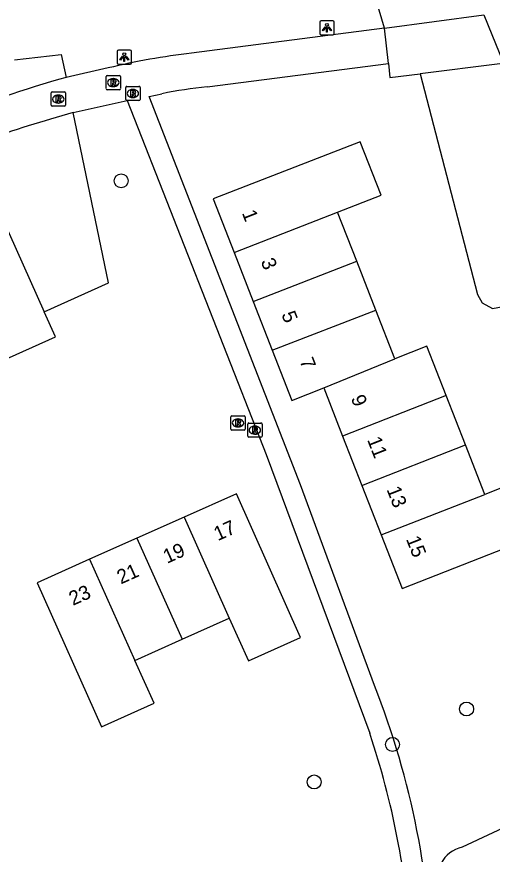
# Model space of a CAD drawing. Extents: x 159451 to 160663, y 388402 to 389723.
# Drawn here: x 159555.6 to 159588.9, y 389199.9 to 389258.6 of the extents above; entities that cross this region are included whole.
import ezdxf

# ---------------------------------------------------------------- set-up
doc = ezdxf.new("R2010")
doc.units = 0
for name, color, linetype in [('IMGEO_Boom', 7, 'Continuous'), ('IMGEO_Lichtpunt', 7, 'Continuous'), ('IMGEO_Meer_plas_ven_vijver', 7, 'Continuous'), ('IMGEO_Pand', 7, 'Continuous'), ('IMGEO_Pand_nummerreeks', 7, 'Continuous'), ('IMGEO_Rijbaan_lokaal_gesloten', 7, 'Continuous'), ('IMGEO_Rijbaan_lokaal_halfverhard', 7, 'Continuous'), ('IMGEO_Rioolput', 7, 'Continuous')]:
    doc.layers.add(name, color=color, linetype=linetype)

msp = doc.modelspace()

# ---------------------------------------------------------------- linework, layer by layer
at = {"layer": 'IMGEO_Boom'}
for centre in [(159562.963, 389247.093), (159587.153, 389210.105), (159581.959, 389207.626), (159576.482, 389204.996)]:
    msp.add_circle(centre, 0.489, dxfattribs=at)
at = {"layer": 'IMGEO_Lichtpunt'}
for p, q in [((159576.876, 389258.208), (159576.876, 389257.401)), ((159576.876, 389258.208), (159576.876, 389257.401)), ((159577.778, 389258.303), (159576.97, 389258.303)), ((159577.778, 389258.303), (159576.97, 389258.303)), ((159577.872, 389257.401), (159577.872, 389258.208)), ((159577.872, 389257.401), (159577.872, 389258.208)), ((159576.97, 389257.307), (159577.778, 389257.307)), ((159576.97, 389257.307), (159577.778, 389257.307)), ((159562.681, 389256.155), (159562.681, 389255.348)), ((159562.681, 389256.155), (159562.681, 389255.348)), ((159563.583, 389256.25), (159562.775, 389256.25)), ((159563.583, 389256.25), (159562.775, 389256.25)), ((159563.677, 389255.348), (159563.677, 389256.155)), ((159563.677, 389255.348), (159563.677, 389256.155)), ((159562.775, 389255.254), (159563.583, 389255.254)), ((159562.775, 389255.254), (159563.583, 389255.254))]:
    msp.add_line(p, q, dxfattribs=at)
for points in [[(159577.25, 389257.872), (159577.289, 389257.844), (159577.101, 389257.582), (159577.063, 389257.609), (159577.25, 389257.872)], [(159577.352, 389257.824), (159577.399, 389257.824), (159577.399, 389257.502), (159577.352, 389257.502), (159577.352, 389257.824)], [(159577.462, 389257.844), (159577.5, 389257.871), (159577.687, 389257.609), (159577.648, 389257.581), (159577.462, 389257.844)], [(159563.055, 389255.819), (159563.094, 389255.791), (159562.906, 389255.529), (159562.868, 389255.556), (159563.055, 389255.819)], [(159563.157, 389255.771), (159563.204, 389255.771), (159563.204, 389255.449), (159563.157, 389255.449), (159563.157, 389255.771)], [(159563.267, 389255.791), (159563.305, 389255.818), (159563.492, 389255.556), (159563.453, 389255.528), (159563.267, 389255.791)]]:
    msp.add_lwpolyline(points, dxfattribs=at)
for centre in [(159577.375, 389258.006), (159563.18, 389255.953)]:
    msp.add_circle(centre, 0.0994, dxfattribs=at)
for centre, start, end in [((159576.97, 389258.208), 90, 180), ((159576.97, 389258.208), 90, 180), ((159577.778, 389258.208), 0, 90), ((159577.778, 389258.208), 0, 90), ((159576.97, 389257.401), 180, 270), ((159576.97, 389257.401), 180, 270), ((159577.778, 389257.401), 270, 0), ((159577.778, 389257.401), 270, 360), ((159562.775, 389256.155), 90, 180), ((159562.775, 389256.155), 90, 180), ((159563.583, 389256.155), 0, 90), ((159563.583, 389256.155), 0, 90), ((159562.775, 389255.348), 180, 270), ((159562.775, 389255.348), 180, 270), ((159563.583, 389255.348), 270, 0), ((159563.583, 389255.348), 270, 360)]:
    msp.add_arc(centre, 0.0946, start, end, dxfattribs=at)
at = {"layer": 'IMGEO_Meer_plas_ven_vijver'}
for points in [[(159581.411, 389257.784), (159575.559, 389277.502), (159573.786, 389277.496)], [(159583.906, 389254.592), (159587.915, 389239.139), (159588.252, 389238.537), (159588.958, 389238.151), (159590.332, 389238.414), (159596.055, 389223.424)], [(159607.369, 389206.712), (159599.834, 389206.945), (159595.441, 389204.453), (159586.831, 389200.427)]]:
    msp.add_lwpolyline(points, dxfattribs=at)
msp.add_arc((159587.317, 389198.287), 2.194, 102.79301, 202.11589, dxfattribs=at)
at = {"layer": 'IMGEO_Pand'}
for points in [[(159578.122, 389244.887), (159581.176, 389246.078), (159579.696, 389249.831), (159569.411, 389245.821), (159570.876, 389242.061)], [(159549.724, 389244.959), (159553.631, 389246.699), (159557.562, 389237.923)], [(159570.876, 389242.061), (159578.122, 389244.887)], [(159579.454, 389241.465), (159578.122, 389244.887)], [(159570.876, 389242.061), (159572.208, 389238.644)], [(159572.208, 389238.644), (159579.454, 389241.465)], [(159580.787, 389238.042), (159579.454, 389241.465)], [(159572.208, 389238.644), (159573.541, 389235.222)], [(159554.447, 389234.413), (159558.351, 389236.161), (159557.562, 389237.923)], [(159573.541, 389235.222), (159580.787, 389238.042)], [(159582.119, 389234.62), (159580.787, 389238.042)], [(159573.541, 389235.222), (159574.908, 389231.714), (159577.145, 389232.586)], [(159585.725, 389232.05), (159584.374, 389235.507), (159582.119, 389234.62)], [(159577.145, 389232.586), (159582.119, 389234.62)], [(159577.145, 389232.586), (159578.465, 389229.213)], [(159585.725, 389232.05), (159578.465, 389229.213)], [(159587.076, 389228.593), (159585.725, 389232.05)], [(159578.465, 389229.213), (159579.818, 389225.756)], [(159579.818, 389225.756), (159587.076, 389228.593)], [(159588.427, 389225.136), (159587.076, 389228.593)], [(159581.17, 389222.301), (159582.637, 389218.552), (159592.944, 389222.587), (159591.484, 389226.33), (159588.427, 389225.136)], [(159579.818, 389225.756), (159581.17, 389222.301)], [(159570.533, 389216.466), (159571.872, 389213.475), (159575.526, 389215.111), (159571.032, 389225.175), (159567.367, 389223.539)], [(159581.17, 389222.301), (159588.427, 389225.136)], [(159567.367, 389223.539), (159564.059, 389222.063)], [(159567.367, 389223.539), (159570.533, 389216.466)], [(159564.059, 389222.063), (159560.751, 389220.586)], [(159564.059, 389222.063), (159567.228, 389214.986)], [(159560.751, 389220.586), (159557.07, 389218.943), (159561.582, 389208.865), (159565.263, 389210.512), (159563.922, 389213.506)], [(159560.751, 389220.586), (159563.922, 389213.506)], [(159567.228, 389214.986), (159570.533, 389216.466)], [(159563.922, 389213.506), (159567.228, 389214.986)]]:
    msp.add_lwpolyline(points, dxfattribs=at)
at = {"layer": 'IMGEO_Rijbaan_lokaal_gesloten'}
for points in [[(159581.411, 389257.784), (159588.35, 389258.709)], [(159588.35, 389258.709), (159589.73, 389255.325)], [(159581.411, 389257.784), (159567.894, 389256.022)], [(159581.675, 389255.309), (159581.411, 389257.784)], [(159568.993, 389253.682), (159581.675, 389255.309)], [(159581.675, 389255.309), (159581.78, 389254.325), (159583.906, 389254.592)], [(159589.472, 389255.292), (159583.906, 389254.592)], [(159562.054, 389254.997), (159559.116, 389254.331)], [(159580.698, 389211.752), (159575.523, 389225.793), (159564.916, 389253.004), (159565.813, 389253.186)], [(159559.597, 389251.864), (159563.374, 389252.707), (159573.107, 389227.927), (159580.373, 389208.403)]]:
    msp.add_lwpolyline(points, dxfattribs=at)
for centre, radius, start, end in [((159573.278, 389208.199), 48.125, 96.42296, 103.48665), ((159584.912, 389163.233), 94.68, 105.81014, 111.33379), ((159573.115, 389216.814), 37.098, 96.37912, 101.35142), ((159582.261, 389169.306), 85.612, 105.35087, 114.11468), ((159526.948, 389190.449), 57.817, 0.63291, 21.61987), ((159525.683, 389190.082), 57.677, 3.49045, 18.52015)]:
    msp.add_arc(centre, radius, start, end, dxfattribs=at)
at = {"layer": 'IMGEO_Rijbaan_lokaal_halfverhard'}
for points in [[(159555.492, 389255.556), (159558.754, 389255.947), (159559.116, 389254.331)], [(159557.562, 389237.923), (159562.085, 389239.938), (159559.597, 389251.864)]]:
    msp.add_lwpolyline(points, dxfattribs=at)
at = {"layer": 'IMGEO_Rioolput'}
for p, q in [((159561.908, 389253.543), (159561.908, 389254.395)), ((159561.983, 389254.469), (159562.835, 389254.469)), ((159562.396, 389254.249), (159562.421, 389254.249)), ((159562.909, 389254.395), (159562.909, 389253.543)), ((159562.835, 389253.469), (159561.983, 389253.469)), ((159562.419, 389253.689), (159562.394, 389253.689)), ((159563.282, 389252.779), (159563.282, 389253.631)), ((159563.357, 389253.705), (159564.209, 389253.705)), ((159563.77, 389253.485), (159563.795, 389253.485)), ((159564.283, 389253.631), (159564.283, 389252.779)), ((159558.058, 389252.391), (159558.058, 389253.243)), ((159558.133, 389253.317), (159558.985, 389253.317)), ((159558.546, 389253.097), (159558.571, 389253.097)), ((159559.059, 389253.243), (159559.059, 389252.391)), ((159563.793, 389252.925), (159563.768, 389252.925)), ((159558.985, 389252.317), (159558.133, 389252.317)), ((159558.569, 389252.537), (159558.544, 389252.537)), ((159564.209, 389252.705), (159563.357, 389252.705)), ((159570.642, 389229.707), (159570.642, 389230.559)), ((159570.717, 389230.633), (159571.569, 389230.633)), ((159571.643, 389230.559), (159571.643, 389229.707)), ((159571.13, 389230.413), (159571.155, 389230.413)), ((159571.823, 389229.206), (159571.823, 389230.058)), ((159571.898, 389230.132), (159572.75, 389230.132)), ((159572.311, 389229.912), (159572.336, 389229.912)), ((159572.824, 389230.058), (159572.824, 389229.206)), ((159571.569, 389229.633), (159570.717, 389229.633)), ((159571.153, 389229.853), (159571.128, 389229.853)), ((159572.334, 389229.352), (159572.309, 389229.352)), ((159572.75, 389229.132), (159571.898, 389229.132))]:
    msp.add_line(p, q, dxfattribs=at)
for points in [[(159561.908, 389253.543), (159561.908, 389254.395)], [(159561.983, 389254.469), (159562.835, 389254.469)], [(159562.497, 389254.167), (159562.245, 389254.169), (159562.245, 389253.769)], [(159562.423, 389254.088), (159562.369, 389254.088), (159562.369, 389254.007)], [(159562.369, 389254.007), (159562.421, 389254.007)], [(159562.909, 389254.395), (159562.909, 389253.543)], [(159562.835, 389253.469), (159561.983, 389253.469)], [(159562.245, 389253.769), (159562.369, 389253.769), (159562.369, 389253.931), (159562.38, 389253.931)], [(159562.427, 389253.902), (159562.498, 389253.769), (159562.638, 389253.769), (159562.573, 389253.895)], [(159563.282, 389252.779), (159563.282, 389253.631)], [(159563.357, 389253.705), (159564.209, 389253.705)], [(159563.871, 389253.403), (159563.619, 389253.405), (159563.619, 389253.005)], [(159564.283, 389253.631), (159564.283, 389252.779)], [(159558.058, 389252.391), (159558.058, 389253.243)], [(159558.133, 389253.317), (159558.985, 389253.317)], [(159558.647, 389253.015), (159558.395, 389253.017), (159558.395, 389252.617)], [(159558.395, 389252.617), (159558.519, 389252.617), (159558.519, 389252.779), (159558.53, 389252.779)], [(159558.573, 389252.936), (159558.519, 389252.936), (159558.519, 389252.855)], [(159558.519, 389252.855), (159558.571, 389252.855)], [(159559.059, 389253.243), (159559.059, 389252.391)], [(159563.619, 389253.005), (159563.743, 389253.005), (159563.743, 389253.167), (159563.754, 389253.167)], [(159563.797, 389253.324), (159563.743, 389253.324), (159563.743, 389253.243)], [(159563.743, 389253.243), (159563.795, 389253.243)], [(159563.801, 389253.138), (159563.872, 389253.005), (159564.012, 389253.005), (159563.947, 389253.131)], [(159558.985, 389252.317), (159558.133, 389252.317)], [(159558.577, 389252.75), (159558.648, 389252.617), (159558.788, 389252.617), (159558.723, 389252.743)], [(159564.209, 389252.705), (159563.357, 389252.705)], [(159570.642, 389229.707), (159570.642, 389230.559)], [(159570.717, 389230.633), (159571.569, 389230.633)], [(159571.643, 389230.559), (159571.643, 389229.707)], [(159571.231, 389230.331), (159570.979, 389230.333), (159570.979, 389229.933)], [(159570.979, 389229.933), (159571.103, 389229.933), (159571.103, 389230.095), (159571.114, 389230.095)], [(159571.157, 389230.252), (159571.103, 389230.252), (159571.103, 389230.171)], [(159571.103, 389230.171), (159571.155, 389230.171)], [(159571.161, 389230.066), (159571.232, 389229.933), (159571.372, 389229.933), (159571.307, 389230.059)], [(159571.823, 389229.206), (159571.823, 389230.058)], [(159571.898, 389230.132), (159572.75, 389230.132)], [(159572.824, 389230.058), (159572.824, 389229.206)], [(159571.569, 389229.633), (159570.717, 389229.633)], [(159572.412, 389229.83), (159572.16, 389229.832), (159572.16, 389229.432)], [(159572.16, 389229.432), (159572.284, 389229.432), (159572.284, 389229.594), (159572.295, 389229.594)], [(159572.338, 389229.751), (159572.284, 389229.751), (159572.284, 389229.67)], [(159572.284, 389229.67), (159572.336, 389229.67)], [(159572.342, 389229.565), (159572.413, 389229.432), (159572.553, 389229.432), (159572.488, 389229.558)], [(159572.75, 389229.132), (159571.898, 389229.132)]]:
    msp.add_lwpolyline(points, dxfattribs=at)
for centre, radius, start, end in [((159561.985, 389254.393), 0.0765, 91.55205, 178.44795), ((159561.985, 389254.393), 0.0765, 91.55205, 178.44795), ((159562.405, 389254.196), 0.19, 274.7715, 282.96867), ((159562.429, 389253.992), 0.0964, 77.00612, 93.18647), ((159562.443, 389254.049), 0.0378, 276.66336, 79.67722), ((159562.496, 389254.057), 0.109, 350.36119, 89.41601), ((159562.494, 389254.057), 0.112, 277.58423, 350.98172), ((159562.478, 389253.842), 0.108, 29.51342, 73.79051), ((159562.833, 389254.393), 0.0765, 1.55205, 88.44795), ((159562.833, 389254.393), 0.0765, 1.55205, 88.44795), ((159561.985, 389253.545), 0.0765, 181.55205, 268.44795), ((159561.985, 389253.545), 0.0765, 181.55205, 268.44795), ((159562.379, 389253.878), 0.0533, 26.02933, 88.69889), ((159562.833, 389253.545), 0.0765, 271.55205, 358.44795), ((159562.833, 389253.545), 0.0765, 271.55205, 358.44795), ((159563.359, 389253.629), 0.0765, 91.55205, 178.44795), ((159563.359, 389253.629), 0.0765, 91.55205, 178.44795), ((159563.87, 389253.293), 0.109, 350.36119, 89.41601), ((159564.207, 389253.629), 0.0765, 1.55205, 88.44795), ((159564.207, 389253.629), 0.0765, 1.55205, 88.44795), ((159558.135, 389253.241), 0.0765, 91.55205, 178.44795), ((159558.135, 389253.241), 0.0765, 91.55205, 178.44795), ((159558.529, 389252.726), 0.0533, 26.02933, 88.69889), ((159558.555, 389253.044), 0.19, 274.7715, 282.96867), ((159558.579, 389252.84), 0.0964, 77.00612, 93.18647), ((159558.593, 389252.897), 0.0378, 276.66336, 79.67722), ((159558.646, 389252.905), 0.109, 350.36119, 89.41601), ((159558.644, 389252.905), 0.112, 277.58423, 350.98172), ((159558.628, 389252.69), 0.108, 29.51342, 73.79051), ((159558.983, 389253.241), 0.0765, 1.55205, 88.44795), ((159558.983, 389253.241), 0.0765, 1.55205, 88.44795), ((159563.359, 389252.781), 0.0765, 181.55205, 268.44795), ((159563.359, 389252.781), 0.0765, 181.55205, 268.44795), ((159563.753, 389253.114), 0.0533, 26.02933, 88.69889), ((159563.779, 389253.432), 0.19, 274.7715, 282.96867), ((159563.803, 389253.228), 0.0964, 77.00612, 93.18647), ((159563.817, 389253.285), 0.0378, 276.66336, 79.67722), ((159563.868, 389253.293), 0.112, 277.58423, 350.98172), ((159563.852, 389253.078), 0.108, 29.51342, 73.79051), ((159564.207, 389252.781), 0.0765, 271.55205, 358.44795), ((159564.207, 389252.781), 0.0765, 271.55205, 358.44795), ((159558.135, 389252.393), 0.0765, 181.55205, 268.44795), ((159558.135, 389252.393), 0.0765, 181.55205, 268.44795), ((159558.983, 389252.393), 0.0765, 271.55205, 358.44795), ((159558.983, 389252.393), 0.0765, 271.55205, 358.44795), ((159570.719, 389230.557), 0.0765, 91.55205, 178.44795), ((159570.719, 389230.557), 0.0765, 91.55205, 178.44795), ((159571.567, 389230.557), 0.0765, 1.55205, 88.44795), ((159571.567, 389230.557), 0.0765, 1.55205, 88.44795), ((159571.113, 389230.042), 0.0533, 26.02933, 88.69889), ((159571.139, 389230.36), 0.19, 274.7715, 282.96867), ((159571.163, 389230.156), 0.0964, 77.00612, 93.18647), ((159571.177, 389230.213), 0.0378, 276.66336, 79.67722), ((159571.23, 389230.221), 0.109, 350.36119, 89.41601), ((159571.228, 389230.221), 0.112, 277.58423, 350.98172), ((159571.212, 389230.006), 0.108, 29.51342, 73.79051), ((159571.9, 389230.056), 0.0765, 91.55205, 178.44795), ((159571.9, 389230.056), 0.0765, 91.55205, 178.44795), ((159572.748, 389230.056), 0.0765, 1.55205, 88.44795), ((159572.748, 389230.056), 0.0765, 1.55205, 88.44795), ((159570.719, 389229.709), 0.0765, 181.55205, 268.44795), ((159570.719, 389229.709), 0.0765, 181.55205, 268.44795), ((159571.567, 389229.709), 0.0765, 271.55205, 358.44795), ((159571.567, 389229.709), 0.0765, 271.55205, 358.44795), ((159572.294, 389229.541), 0.0533, 26.02933, 88.69889), ((159572.32, 389229.859), 0.19, 274.7715, 282.96867), ((159572.344, 389229.655), 0.0964, 77.00612, 93.18647), ((159572.358, 389229.712), 0.0378, 276.66336, 79.67722), ((159572.411, 389229.72), 0.109, 350.36119, 89.41601), ((159572.409, 389229.72), 0.112, 277.58423, 350.98172), ((159572.393, 389229.505), 0.108, 29.51342, 73.79051), ((159571.9, 389229.208), 0.0765, 181.55205, 268.44795), ((159571.9, 389229.208), 0.0765, 181.55205, 268.44795), ((159572.748, 389229.208), 0.0765, 271.55205, 358.44795), ((159572.748, 389229.208), 0.0765, 271.55205, 358.44795)]:
    msp.add_arc(centre, radius, start, end, dxfattribs=at)
for centre, major_axis, ratio, start_param, end_param in [((159562.395, 389253.969), (-0.387, 0.002), 0.722429, 4.712389, 7.853982), ((159562.42, 389253.969), (-0.39, 0.002), 0.717154, 1.570796, 4.712389), ((159563.769, 389253.205), (-0.387, 0.002), 0.722429, 4.712389, 7.853982), ((159563.794, 389253.205), (-0.39, 0.002), 0.717154, 1.570796, 4.712389), ((159558.545, 389252.817), (-0.387, 0.002), 0.722429, 4.712389, 7.853982), ((159558.57, 389252.817), (-0.39, 0.002), 0.717154, 1.570796, 4.712389), ((159571.129, 389230.133), (-0.387, 0.002), 0.722429, 4.712389, 7.853982), ((159571.154, 389230.133), (-0.39, 0.002), 0.717154, 1.570796, 4.712389), ((159572.31, 389229.632), (-0.387, 0.002), 0.722429, 4.712389, 7.853982), ((159572.335, 389229.632), (-0.39, 0.002), 0.717154, 1.570796, 4.712389)]:
    msp.add_ellipse(centre, major_axis=major_axis, ratio=ratio, start_param=start_param, end_param=end_param, dxfattribs=at)

# ---------------------------------------------------------------- texts
at = {"layer": 'IMGEO_Pand_nummerreeks'}
for s, rotation, p in [('1', 291.2909, (159571.403, 389244.841)), ('3', 291.2909, (159572.722, 389241.455)), ('5', 291.2909, (159574.169, 389237.742)), ('7', 291.2909, (159575.436, 389234.49)), ('9', 291.37112, (159579.033, 389231.878)), ('11', 291.37112, (159580.175, 389228.96)), ('13', 291.37112, (159581.534, 389225.488)), ('17', 24.05277, (159569.723, 389221.853)), ('19', 24.05277, (159566.172, 389220.268)), ('15', 291.37112, (159582.895, 389222.01)), ('21', 24.05277, (159562.937, 389218.824)), ('23', 24.05277, (159559.575, 389217.323))]:
    msp.add_text(s, height=1, rotation=rotation, dxfattribs=at).set_placement(p)

doc.saveas('drawing.dxf')
